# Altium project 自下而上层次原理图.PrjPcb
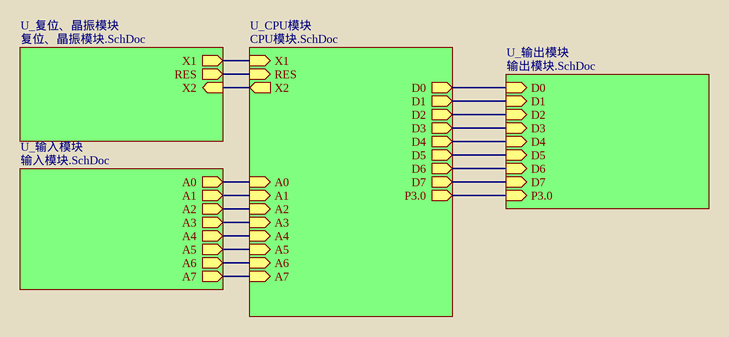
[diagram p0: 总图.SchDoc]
5 sheets, 34 parts. Net scope: hierarchical (ports join the sheet entries above them; power ports are global).
Board file: 层次电路.PcbDoc
Sheets:
  总图.SchDoc
    U_CPU模块 = CPU模块.SchDoc
    U_复位、晶振模块 = 复位、晶振模块.SchDoc
    U_输入模块 = 输入模块.SchDoc
    U_输出模块 = 输出模块.SchDoc

## Sheet 总图.SchDoc
size A3; Address1: 梁福海; Address2: 202411067; Address3: 24应电（二年制）

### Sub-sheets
U_CPU模块 = CPU模块.SchDoc: X1 (in), X2 (out), RES (in), P3.0 (out), D0 (out), D1 (out), D2 (out), D3 (out), D4 (out), D5 (out), D6 (out), D7 (out), A0 (in), A1 (in), A2 (in), A3 (in), A4 (in), A5 (in), A6 (in), A7 (in)
U_复位、晶振模块 = 复位、晶振模块.SchDoc: X1 (out), X2 (in), RES (out)
U_输入模块 = 输入模块.SchDoc: A0 (out), A1 (out), A2 (out), A3 (out), A4 (out), A5 (out), A6 (out), A7 (out)
U_输出模块 = 输出模块.SchDoc: D0 (in), D1 (in), D2 (in), D3 (in), D4 (in), D5 (in), D6 (in), D7 (in), P3.0 (in)

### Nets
A0: sheet U_CPU模块/A0, sheet U_输入模块/A0
A1: sheet U_CPU模块/A1, sheet U_输入模块/A1
A2: sheet U_CPU模块/A2, sheet U_输入模块/A2
A3: sheet U_CPU模块/A3, sheet U_输入模块/A3
A4: sheet U_CPU模块/A4, sheet U_输入模块/A4
A5: sheet U_CPU模块/A5, sheet U_输入模块/A5
A6: sheet U_CPU模块/A6, sheet U_输入模块/A6
A7: sheet U_CPU模块/A7, sheet U_输入模块/A7
D0: sheet U_CPU模块/D0, sheet U_输出模块/D0
D1: sheet U_CPU模块/D1, sheet U_输出模块/D1
D2: sheet U_CPU模块/D2, sheet U_输出模块/D2
D3: sheet U_CPU模块/D3, sheet U_输出模块/D3
D4: sheet U_CPU模块/D4, sheet U_输出模块/D4
D5: sheet U_CPU模块/D5, sheet U_输出模块/D5
D6: sheet U_CPU模块/D6, sheet U_输出模块/D6
D7: sheet U_CPU模块/D7, sheet U_输出模块/D7
P30: sheet U_CPU模块/P3.0, sheet U_输出模块/P3.0
NetC1_2: sheet U_CPU模块/X1, sheet U_复位、晶振模块/X1
NetC2_2: sheet U_CPU模块/X2, sheet U_复位、晶振模块/X2
NetC3_2: sheet U_CPU模块/RES, sheet U_复位、晶振模块/RES

## Sheet CPU模块.SchDoc
size A3; Address1: 梁福海; Address2: 202411067; Address3: 24应电（二年制）
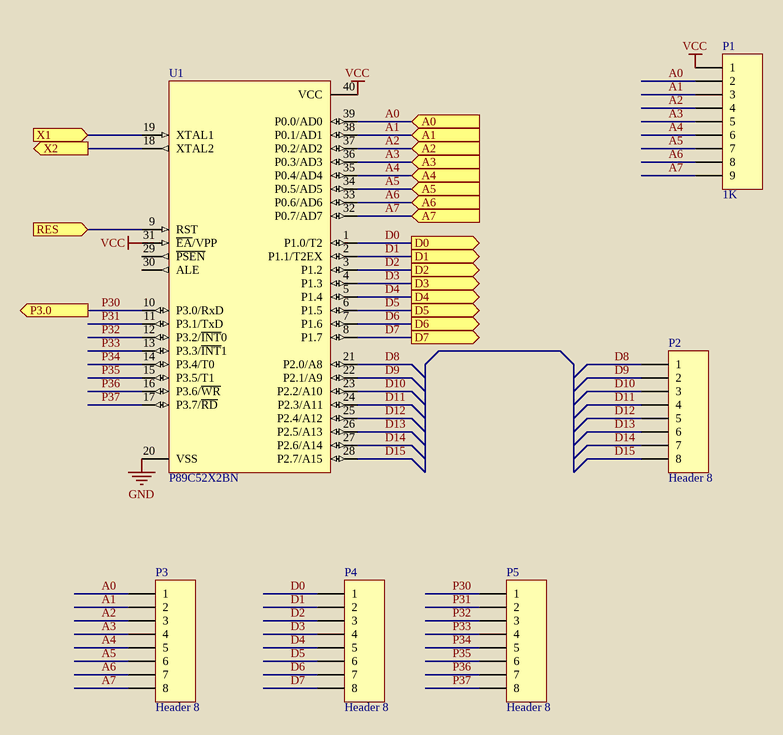
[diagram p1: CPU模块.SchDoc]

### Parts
P1  1K  [HDR1X9]
P2  Header 8  [HDR1X8]
P3  Header 8  [HDR1X8]
P4  Header 8  [HDR1X8]
P5  Header 8  [HDR1X8]
U1  P89C52X2BN  [DIP40]

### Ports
A0 (in), A1 (in), A2 (in), A3 (in), A4 (in), A5 (in), A6 (in), A7 (in), D0 (out), D1 (out), D2 (out), D3 (out), D4 (out), D5 (out), D6 (out), D7 (out), P3.0 (out), RES (in), X1 (in), X2 (out)

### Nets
GND: U1.20(VSS)
VCC: P1.1 U1.31(~{EA}/VPP) U1.40(VCC)
A0: P1.2 P3.1 U1.39(P0.0/AD0) ; port A0
A1: P1.3 P3.2 U1.38(P0.1/AD1) ; port A1
A2: P1.4 P3.3 U1.37(P0.2/AD2) ; port A2
A3: P1.5 P3.4 U1.36(P0.3/AD3) ; port A3
A4: P1.6 P3.5 U1.35(P0.4/AD4) ; port A4
A5: P1.7 P3.6 U1.34(P0.5/AD5) ; port A5
A6: P1.8 P3.7 U1.33(P0.6/AD6) ; port A6
A7: P1.9 P3.8 U1.32(P0.7/AD7) ; port A7
D0: P4.1 U1.1(P1.0/T2) ; port D0
D1: P4.2 U1.2(P1.1/T2EX) ; port D1
D2: P4.3 U1.3(P1.2) ; port D2
D3: P4.4 U1.4(P1.3) ; port D3
D4: P4.5 U1.5(P1.4) ; port D4
D5: P4.6 U1.6(P1.5) ; port D5
D6: P4.7 U1.7(P1.6) ; port D6
D7: P4.8 U1.8(P1.7) ; port D7
D8: P2.1 U1.21(P2.0/A8)
D9: P2.2 U1.22(P2.1/A9)
D10: P2.3 U1.23(P2.2/A10)
D11: P2.4 U1.24(P2.3/A11)
D12: P2.5 U1.25(P2.4/A12)
D13: P2.6 U1.26(P2.5/A13)
D14: P2.7 U1.27(P2.6/A14)
D15: P2.8 U1.28(P2.7/A15)
P30: P5.1 U1.10(P3.0/RxD) ; port P3.0
P31: P5.2 U1.11(P3.1/TxD)
P32: P5.3 U1.12(P3.2/~{INT}0)
P33: P5.4 U1.13(P3.3/~{INT}1)
P34: P5.5 U1.14(P3.4/T0)
P35: P5.6 U1.15(P3.5/T1)
P36: P5.7 U1.16(P3.6/~{WR})
P37: P5.8 U1.17(P3.7/~{RD})
NetC1_2: U1.19(XTAL1) ; port X1
NetC2_2: U1.18(XTAL2) ; port X2
NetC3_2: U1.9(RST) ; port RES

Not connected (* = marked no-connect by the designer): U1 29(~{PSEN}) 30(ALE)

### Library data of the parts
P1 = Header 9: Header, 9-Pin
P2-P5 = Header 8: Header, 8-Pin
U1 = P89C52X2BN: 80C51 8-Bit Flash Microcontroller Family, 8 kB Flash; Package Information: Latest Revision: Aug-2000; Code - JEDEC: MO-015

## Sheet 复位、晶振模块.SchDoc
size A3; Address1: 梁福海; Address2: 202411067; Address3: 24应电（二年制）
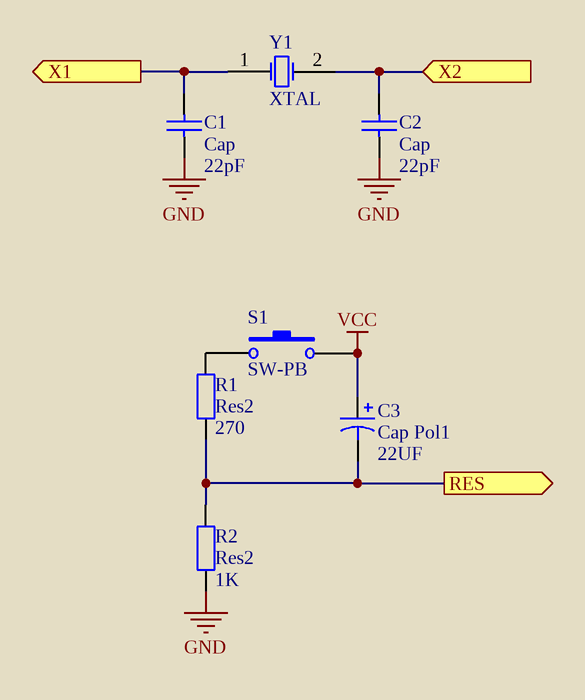
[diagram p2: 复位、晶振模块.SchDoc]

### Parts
C1  Cap  value 22pF  [RAD-0.3]
C2  Cap  value 22pF  [RAD-0.3]
C3  Cap Pol1  value 22UF  [RB7.6-15]
R1  Res2  value 270  [AXIAL-0.4]
R2  Res2  value 1K  [AXIAL-0.4]
S1  SW-PB  [SPST-2]
Y1  XTAL  [R38]

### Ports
RES (out), X1 (out), X2 (in)

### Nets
GND: C1.1 C2.1 R2.1
VCC: C3.1 S1.2
NetC1_2: C1.2 Y1.1(OSC1) ; port X1
NetC2_2: C2.2 Y1.2(OSC2) ; port X2
NetC3_2: C3.2 R1.1 R2.2 ; port RES
NetR1_2: R1.2 S1.1

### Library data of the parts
C1 C2 = Cap: Capacitor
C3 = Cap Pol1: Polarized Capacitor (Radial)
R1 R2 = Res2: Resistor
S1 = SW-PB: Switch
Y1 = XTAL: Crystal Oscillator

## Sheet 输入模块.SchDoc
size A3; Address1: 梁福海; Address2: 202411067; Address3: 24应电（二年制）
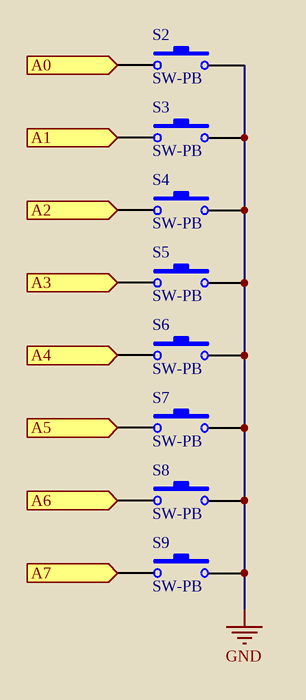
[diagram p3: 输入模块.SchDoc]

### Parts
S2  SW-PB  [SPST-2]
S3  SW-PB  [SPST-2]
S4  SW-PB  [SPST-2]
S5  SW-PB  [SPST-2]
S6  SW-PB  [SPST-2]
S7  SW-PB  [SPST-2]
S8  SW-PB  [SPST-2]
S9  SW-PB  [SPST-2]

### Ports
A0 (out), A1 (out), A2 (out), A3 (out), A4 (out), A5 (out), A6 (out), A7 (out)

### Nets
GND: S2.2 S3.2 S4.2 S5.2 S6.2 S7.2 S8.2 S9.2
A0: S2.1 ; port A0
A1: S3.1 ; port A1
A2: S4.1 ; port A2
A3: S5.1 ; port A3
A4: S6.1 ; port A4
A5: S7.1 ; port A5
A6: S8.1 ; port A6
A7: S9.1 ; port A7

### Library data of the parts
S2-S9 = SW-PB: Switch

## Sheet 输出模块.SchDoc
size A3; Address1: 梁福海; Address2: 202411067; Address3: 24应电（二年制）
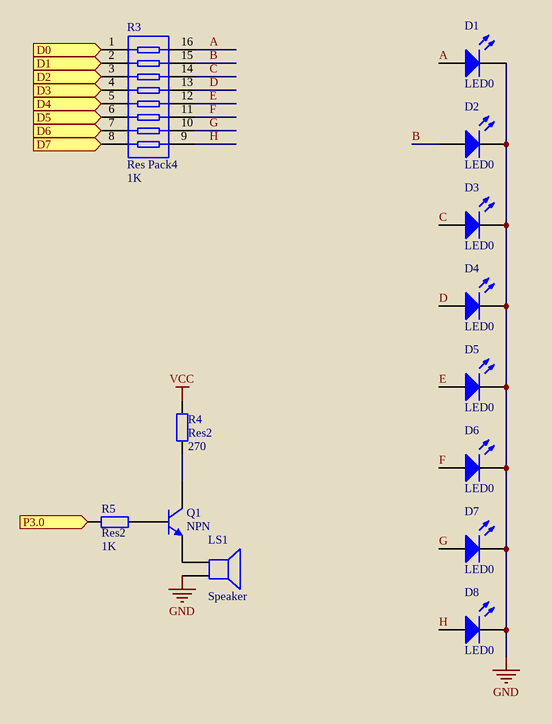
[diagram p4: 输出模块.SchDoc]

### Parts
D1  LED0  [LED-0]
D2  LED0  [LED-0]
D3  LED0  [LED-0]
D4  LED0  [LED-0]
D5  LED0  [LED-0]
D6  LED0  [LED-0]
D7  LED0  [LED-0]
D8  LED0  [LED-0]
LS1  Speaker  [PIN2]
Q1  NPN  [TO-226-AA]
R3  Res Pack4  value 1K  [DIP-16]
R4  Res2  value 270  [AXIAL-0.4]
R5  Res2  value 1K  [AXIAL-0.4]

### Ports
D0 (in), D1 (in), D2 (in), D3 (in), D4 (in), D5 (in), D6 (in), D7 (in), P3.0 (in)

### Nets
GND: D1.2(K) D2.2(K) D3.2(K) D4.2(K) D5.2(K) D6.2(K) D7.2(K) D8.2(K) LS1.2
VCC: R4.2
A: D1.1(A) R3.16
B: D2.1(A) R3.15
C: D3.1(A) R3.14
D: D4.1(A) R3.13
D0: R3.1 ; port D0
D1: R3.2 ; port D1
D2: R3.3 ; port D2
D3: R3.4 ; port D3
D4: R3.5 ; port D4
D5: R3.6 ; port D5
D6: R3.7 ; port D6
D7: R3.8 ; port D7
E: D5.1(A) R3.12
F: D6.1(A) R3.11
G: D7.1(A) R3.10
H: D8.1(A) R3.9
P30: R5.1 ; port P3.0
NetLS1_1: LS1.1 Q1.3(E)
NetQ1_1: Q1.1(C) R4.1
NetQ1_2: Q1.2(B) R5.2

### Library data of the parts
D1-D8 = LED0: Typical INFRARED GaAs LED
LS1 = Speaker: Loudspeaker
Q1 = NPN: NPN Bipolar Transistor
R3 = Res Pack4: Isolated Resistor Network
R4 R5 = Res2: Resistor

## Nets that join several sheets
GND: CPU模块 (U1.20), 复位、晶振模块 (C1.1 C2.1 R2.1), 输入模块 (8 pins), 输出模块 (9 pins)
VCC: CPU模块 (P1.1 U1.31 U1.40), 复位、晶振模块 (C3.1 S1.2), 输出模块 (R4.2)
A0: CPU模块 (P1.2 P3.1 U1.39), 输入模块 (S2.1)
A1: CPU模块 (P1.3 P3.2 U1.38), 输入模块 (S3.1)
A2: CPU模块 (P1.4 P3.3 U1.37), 输入模块 (S4.1)
A3: CPU模块 (P1.5 P3.4 U1.36), 输入模块 (S5.1)
A4: CPU模块 (P1.6 P3.5 U1.35), 输入模块 (S6.1)
A5: CPU模块 (P1.7 P3.6 U1.34), 输入模块 (S7.1)
A6: CPU模块 (P1.8 P3.7 U1.33), 输入模块 (S8.1)
A7: CPU模块 (P1.9 P3.8 U1.32), 输入模块 (S9.1)
D0: CPU模块 (P4.1 U1.1), 输出模块 (R3.1)
D1: CPU模块 (P4.2 U1.2), 输出模块 (R3.2)
D2: CPU模块 (P4.3 U1.3), 输出模块 (R3.3)
D3: CPU模块 (P4.4 U1.4), 输出模块 (R3.4)
D4: CPU模块 (P4.5 U1.5), 输出模块 (R3.5)
D5: CPU模块 (P4.6 U1.6), 输出模块 (R3.6)
D6: CPU模块 (P4.7 U1.7), 输出模块 (R3.7)
D7: CPU模块 (P4.8 U1.8), 输出模块 (R3.8)
NetC1_2: CPU模块 (U1.19), 复位、晶振模块 (C1.2 Y1.1)
NetC2_2: CPU模块 (U1.18), 复位、晶振模块 (C2.2 Y1.2)
NetC3_2: CPU模块 (U1.9), 复位、晶振模块 (C3.2 R1.1 R2.2)
P30: CPU模块 (P5.1 U1.10), 输出模块 (R5.1)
